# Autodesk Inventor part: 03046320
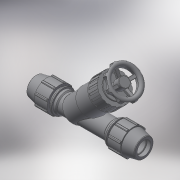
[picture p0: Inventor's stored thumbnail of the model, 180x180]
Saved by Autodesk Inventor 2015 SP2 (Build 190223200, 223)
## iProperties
Created: 2017-02
Part Number: 03046320
Material: Generic
Description: PLASSON ANGLE SEAT VALVE 32-32
Document SubType Name: Modeling
Designer: KIM
Mass: 682.593 g
Surface Area: 1067.27 cm^2
Volume: 682.593 cm^3
Density: 1 g/cm^3
Appearance: Default
Author: KIM
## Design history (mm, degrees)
derived "03046.ipt"
feature "Solid1::03046.ipt"
tag "TaggingFeature1"
body "Solid1"
other parameters: "d_" = 32, "E_" = 64, "H_" = 254, "d187" = 113, "d188" = 135, "d224" = 113, "d160" = 48, "d202" = 68.04, "d214" = 75.6, "d218" = 75.6, "d225" = 75.6, "d226" = 52.92, "d2" = 32, "d4" = 10.58333, "d5" = 25.4, "d7" = 64, "d11" = 3.62857, "d13" = 120 deg, "d14" = 44.8, "d15" = 12 deg, "d16" = 55.68, "d18" = 1.6, "d19" = 35 deg, "d20" = 17.5 deg, "d21" = 59.52, "d23" = 0, "d25" = 360 deg, "d27" = 1.28, "d33" = 0.64, "d42" = 30.48, "d43" = 1.92, "d46" = 0.96, "d67" = 48, "d96" = 5.64444, "d118" = 360 deg, "d121" = 0, "d128" = 254, "d131" = 28.8, "d156" = 0, "d159" = 2, "d161" = 43.2, "d162" = 2.4, "d165" = 126, "d167" = 75.6, "d168" = 22.68, "d169" = 22.68, "d170" = 90 deg, "d171" = 70 deg, "d172" = 18.144, "d173" = 52.92, "d174" = 52.92, "d175" = 68.04, "d176" = 135 deg, "d177" = 60.48, "d178" = 56.7, "d179" = 31.5, "d180" = 126, "d182" = 18.144, "d183" = 49.896, "d190" = 45 deg, "d191" = 30.48, "d192" = 2.8, "d193" = 4.52, "d194" = 2.26, "d195" = 65.9988, "d196" = 45.765, "d198" = 0, "d199" = 28.35, "d200" = 113, "d201" = 101.7, "d204" = 360 deg, "d209" = 0, "d213" = 3.78, "d216" = 360 deg, "d219" = 35.595, "d220" = 64.26, "d221" = 3.39, "d222" = 3.39, "d223" = 6.78, "d227" = 3.39, "d229" = 0, "d230" = 0.7, "d232" = 360 deg, "d234" = 0.7, "d235" = 0.7, "d237" = 360 deg, "d239" = 1.12, "d240" = 0.7, "d241" = 0.7
